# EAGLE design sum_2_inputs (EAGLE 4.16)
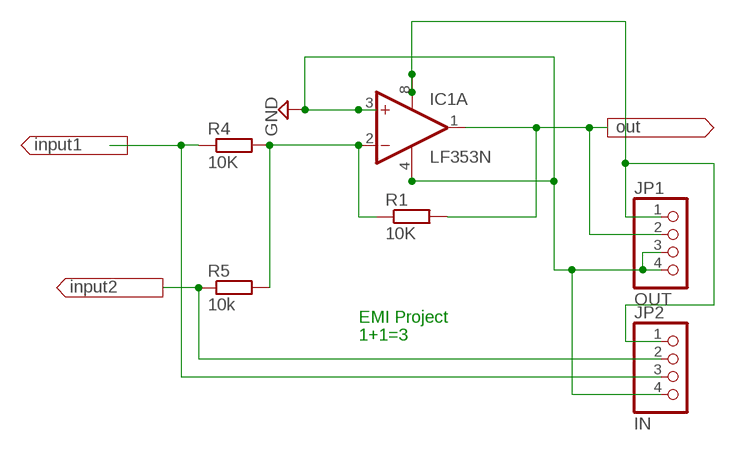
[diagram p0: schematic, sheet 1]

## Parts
IC1  LF353N  [DIL08]
JP1  OUT  PINHD-1X4  [1X04]
JP2  IN  PINHD-1X4  [1X04]
R1  10K  R-EU_0204/7  [0204/7]
R4  10K  R-EU_0204/7  [0204/7]
R5  10k  R-EU_0204/7  [0204/7]

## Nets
GND: IC1.3(A:+IN) IC1.4(P:V-) JP1.3 JP1.4 JP2.4
N$1: IC1.2(A:-IN) R1.1 R4.2 R5.2
N$2: IC1.1(A:OUT) JP1.2 R1.2
N$3: JP2.3 R4.1
N$4: JP2.2 R5.1
N$5: IC1.8(P:V+) JP1.1 JP2.1
Unconnected: IC1.5(B:+IN) IC1.6(B:-IN) IC1.7(B:OUT)

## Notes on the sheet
- EMI Project
- 1+1=3

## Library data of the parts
IC1 = linear:LF353: OP AMP
JP1 JP2 = pinhead:PINHD-1X4: PIN HEADER
R1 R4 R5 = rcl:R-EU_: RESISTOR, European symbol

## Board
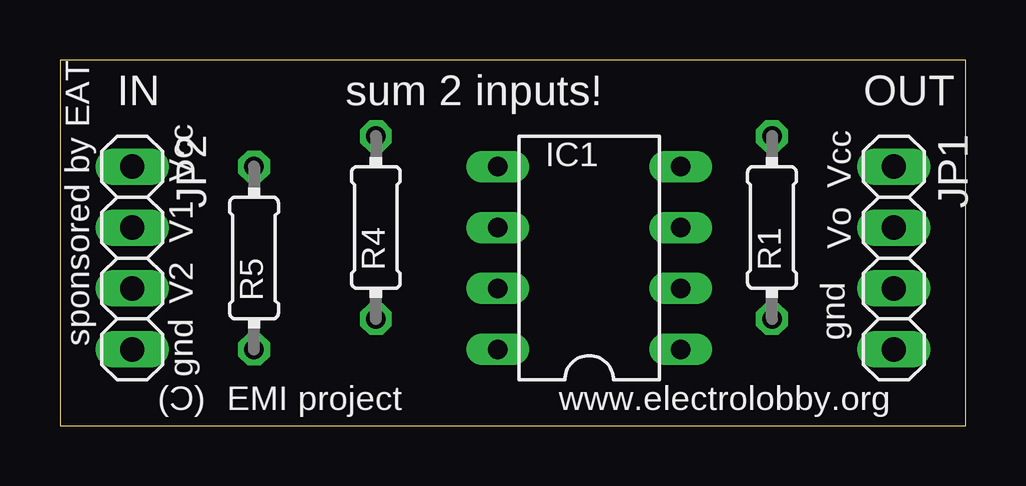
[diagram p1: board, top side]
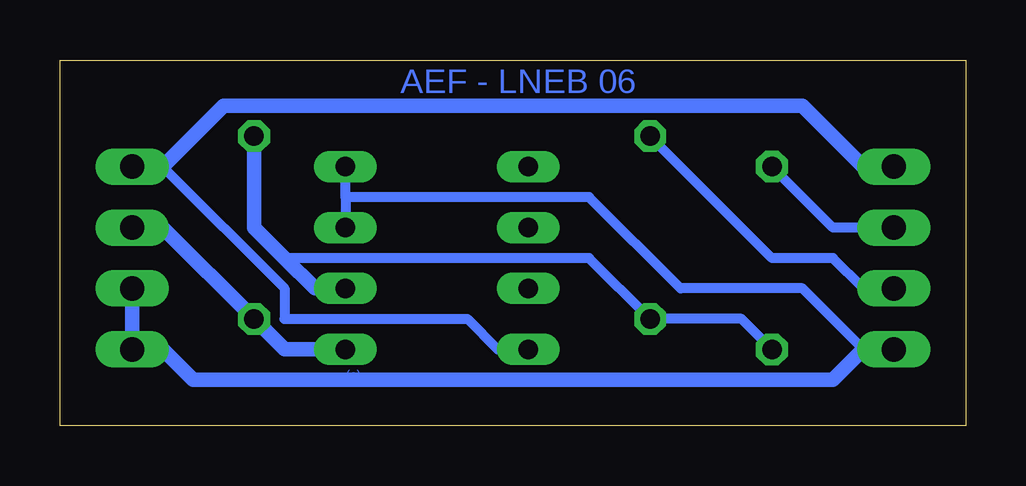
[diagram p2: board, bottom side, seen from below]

Size 37.77 x 15.23 mm. Coordinates in mm from the lower left corner, seen from the top.
Outline: 0,0 37.77,0 37.77,15.23 0,15.23 0,0
Copper layers (1*16): Top 0.035mm / dielectric 1.5mm / Bottom 0.035mm
Design rules "default": minimum track width 10mil, minimum drill 24mil, track to track 8mil, track to pad 8mil, pad to pad 8mil, via to via 8mil, smd to smd 8mil, copper to edge 40mil, drill to drill 8mil, minimum pad ring 10mil, minimum via ring 8mil, stop-mask expansion 4mil, vias tented up to drill 0mil, thermal gap 10mil

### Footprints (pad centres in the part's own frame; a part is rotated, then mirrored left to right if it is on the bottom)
DIL08 = drill 0.813 long: 1 -3.81,-3.81; 2 -1.27,-3.81; 3 1.27,-3.81; 4 3.81,-3.81; 5 3.81,3.81; 6 1.27,3.81; 7 -1.27,3.81; 8 -3.81,3.81
1X04 = drill 1.016 long: 1 -3.81,0; 2 -1.27,0; 3 1.27,0; 4 3.81,0
0204/7 = drill 0.813 octagon: 1 -3.81,0; 2 3.81,0

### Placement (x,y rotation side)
IC1  22.06,6.98 90 top
JP1  34.76,6.98 270 top
JP2  3.01,6.98 270 top
R1  29.68,8.25 270 top
R4  13.17,8.25 270 top
R5  8.09,6.98 270 top

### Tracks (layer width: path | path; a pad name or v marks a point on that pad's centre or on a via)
GND
  Bottom 0.406: 25.87,9.52 IC1.4 | 25.87,9.52 IC1.3 | 4.28,3.17 6.82,5.71 11.9,5.71 15.71,9.52 25.87,9.52
  Bottom 0.61: JP1.3 JP1.4 33.49,3.17 32.22,1.9 5.55,1.9 4.28,3.17 JP2.4
N$1
  Bottom 0.406: R5.2 9.36,4.44 R4.2 15.71,6.98 28.41,6.98
  Bottom 0.61: R1.1 29.68,8.25 28.41,6.98 27.14,5.71 IC1.2
N$2
  Bottom 0.61: IC1.1 28.41,3.17 R1.2 33.49,8.25 JP1.2
N$3
  Bottom 0.406: R4.1 8.09,6.98 5.55,6.98 4.28,5.71 JP2.3
N$4
  Bottom 0.406: R5.1 5.55,8.25 JP2.2
N$5
  Bottom 0.254: 19.52,3.17 IC1.8
  Bottom 0.406: 19.52,3.17 20.79,4.44 28.41,4.44 28.41,5.71 33.49,10.79
  Bottom 0.61: JP2.1 4.28,10.79 6.82,13.33 30.95,13.33 33.49,10.79 JP1.1

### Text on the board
Bottom: AEF - LNEB 06 | (c)
tPlace: sponsored by EAT | sum 2 inputs! | Vcc | Vcc | V1 | Vo | V2 | gnd | gnd | EMI project | www.electrolobby.org
tNames: (C)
